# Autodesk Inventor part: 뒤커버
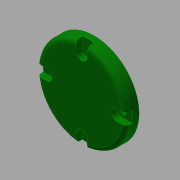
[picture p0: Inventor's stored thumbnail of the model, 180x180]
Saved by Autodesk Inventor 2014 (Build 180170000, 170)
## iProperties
Created: 2019-01
Part Number: 뒤커버
Material: 알루미늄 6061
Document SubType Name: Modeling
Designer: mduedu
Density: 2.71 g/cm^3
Appearance: 진녹색
Mass: 71.8557 g
Surface Area: 92.0216 cm^2
Volume: 26.515 cm^3
Author: mduedu
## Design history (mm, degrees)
sketch "스케치1"
  geometry: L1 (0, 0)-(9, 0); L2 (9, 0)-(9, 32); L3 (9, 32)-(0, 32); L4 (0, 32)-(0, 0); L5 (9, 0)-(12, 0); L6 (12, 0)-(12, 20); L7 (12, 20)-(9, 20); L8 (9, 20)-(9, 0)
  constraints: 16 end point, 4 parallel, 2 horizontal, 2 perpendicular
  dimensions: "d0" = 12 distance between parallel lines of L6 L4; "d2" = 64 diameter of L3 L1; "d3" = 40 diameter of L7 L5; "d4" = 3 distance between parallel lines of L6 L2
revolve "회전1" sketch "스케치1" stored, may be unused: angle "d5" = 90 deg
sketch "스케치4"
  geometry: C1 r 15 at (0, 0); 1 further point
  constraints: 1 centre point, 1 coincident
  dimensions: "d24" = 30 diameter of C1
extrude "돌출1" cut sketch "스케치4" distance "d25" = 6; taper "d26" = 0 deg
fillet "모깎기4" dims "d27" = 3
fillet "모깎기3" dims "d18" = 3
chamfer "모따기2" distance "d28" = 1; stored, may be unused: second distance "d29" = 2, angle "d30" = 45 deg
sketch "스케치3" dims "d19" = 50
  geometry: 6 further points
  constraints: 2 vertical alignment, 1 coincident, 7 other
  dimensions: "d22" = 360 deg dimension on point (0, 0) point (0, 25) (derived)
sketch "스케치5"
  geometry: 4 further points
  constraints: 4 other
hole "구멍1" sketch "스케치5" at (-25, 0), (0, -25), (25, 0), (0, 25) diameter "d31" = 4.5; stored, may be unused: countersink angle "d35" = 90 deg, drill point angle "d37" = 0 deg; dims "d32" = 6, "d33" = 8, "d34" = 4.6, "d36" = 8
sketch "스케치6"
  geometry: L1 (-4, 0)-(-4, 6.749); L2 (4, 0)-(4, 6.749); A1 r 4 centre (0, 0) between (0, 4) and (-4, 0) reference; A2 r 32 centre (0, -25) between (-4, 6.749) and (4, 6.749) reference; A3 r 4 centre (0, 0) between (-4, 0) and (4, 0); A4 r 32 centre (0, -25) between (4, 6.749) and (-4, 6.749); A5 r 4 centre (0, 0) between (4, 0) and (-4, 0); 1 further point
  constraints: 10 point on circle, 4 end point, 3 centre point, 2 coincident, 2 tangent, 1 parallel, 1 vertical
extrude "돌출2" cut sketch "스케치6" stored distance "d38" = 10; taper "d39" = 0 deg
node "솔리드1"
pattern_circular "원형 패턴1" dims angle "d41" = 360 deg
